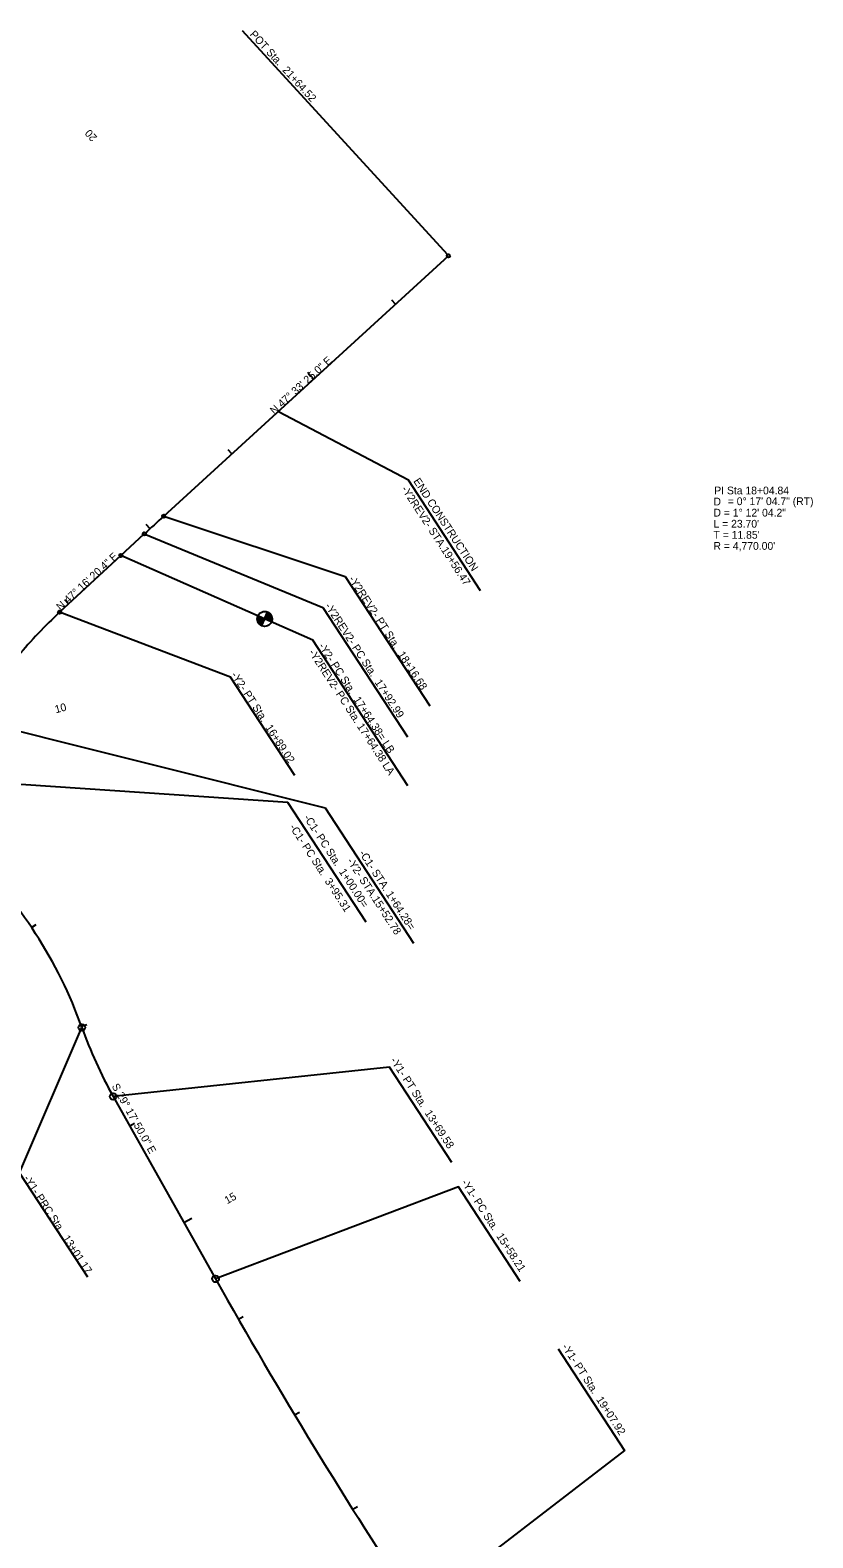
# Model space of a CAD drawing. Extents: x 1636713 to 1642889, y 841520 to 844630.
# Drawn here: x 1640491 to 1641196, y 843029 to 844389 of the extents above; entities that cross this region are included whole.
import ezdxf

# ---------------------------------------------------------------- set-up
doc = ezdxf.new("R2010")
doc.units = 0
for name, color, linetype in [('Exist 4 AWG with gnd feeder circuit in conduit', 7, 'Continuous'), ('Exist 6 AWG with gnd feeder circuit', 7, 'Continuous'), ('Exist 8 AWG with gnd feeder circuit', 7, 'Continuous'), ('Exist 8 AWG with gnd feeder circuit in conduit', 7, 'Continuous'), ('Prop 2 AWG with gnd feeder circuit', 7, 'Continuous'), ('Prop 2 AWG with gnd feeder circuit in conduit', 7, 'Continuous'), ('Prop 4 AWG with gnd feeder circuit', 7, 'Continuous'), ('Prop Clearing and Grubbing', 7, 'Continuous')]:
    doc.layers.add(name, color=color, linetype=linetype)

msp = doc.modelspace()

# ---------------------------------------------------------------- linework, layer by layer
at = {"layer": 'Exist 6 AWG with gnd feeder circuit'}
for p, q in [((1640866.6, 844186.6), (1640682, 844388.4)), ((1640896.6, 843883.4), (1640831.5, 843983.1)), ((1640610.9, 843950.7), (1640774.6, 843896.3)), ((1640593.4, 843934.7), (1640754.5, 843868.4)), ((1640774.6, 843896.3), (1640850.7, 843779.7)), ((1640671.2, 843805.7), (1640517.1, 843864.1)), ((1640701.9, 843858.1), (1640704.6, 843864.3)), ((1640754.5, 843868.4), (1640830.6, 843751.8)), ((1640695.8, 843860.8), (1640701.9, 843858.1)), ((1640699.2, 843852), (1640701.9, 843858.1)), ((1640701.9, 843858.1), (1640699.2, 843852)), ((1640708.1, 843855.4), (1640701.9, 843858.1)), ((1640722.9, 843692.6), (1640411, 843713.6)), ((1640793.3, 843584.7), (1640722.9, 843692.6)), ((1640836.4, 843565.5), (1640756.9, 843687.4))]:
    msp.add_line(p, q, dxfattribs=at)
for points in [[(1640831.5, 843983.1), (1640714.4, 844044.7)], [(1640830.9, 843707.6), (1640745.2, 843838.9), (1640572.4, 843915.3)], [(1640704.7, 843864.2), (1640704.7, 843864.2), (1640702, 843858.1)], [(1640704.8, 843864.2), (1640702.1, 843858)], [(1640704.9, 843864.1), (1640702.2, 843858)], [(1640705, 843864.1), (1640702.3, 843857.9)], [(1640705.2, 843864), (1640702.5, 843857.9)], [(1640705.3, 843863.9), (1640702.6, 843857.8)], [(1640705.4, 843863.9), (1640702.7, 843857.8)], [(1640705.5, 843863.8), (1640702.8, 843857.7)], [(1640705.6, 843863.7), (1640703, 843857.7)], [(1640705.7, 843863.6), (1640703.1, 843857.6)], [(1640705.8, 843863.6), (1640703.2, 843857.6)], [(1640706, 843863.5), (1640703.3, 843857.5)], [(1640706.1, 843863.4), (1640703.4, 843857.4)], [(1640706.2, 843863.3), (1640703.6, 843857.4)], [(1640706.3, 843863.2), (1640703.7, 843857.3)], [(1640706.4, 843863.1), (1640703.8, 843857.3)], [(1640706.5, 843863), (1640703.9, 843857.2)], [(1640706.6, 843862.9), (1640704.1, 843857.2)], [(1640706.7, 843862.8), (1640704.2, 843857.1)], [(1640706.8, 843862.7), (1640704.3, 843857.1)], [(1640706.9, 843862.6), (1640704.4, 843857)], [(1640707, 843862.5), (1640704.5, 843857)], [(1640707.1, 843862.4), (1640704.7, 843856.9)], [(1640707.2, 843862.3), (1640704.8, 843856.8)], [(1640707.3, 843862.1), (1640704.9, 843856.8)], [(1640707.4, 843862), (1640705, 843856.7)], [(1640707.5, 843861.9), (1640705.2, 843856.7)], [(1640707.6, 843861.8), (1640705.3, 843856.6)], [(1640707.6, 843861.6), (1640705.4, 843856.6)], [(1640707.7, 843861.5), (1640705.5, 843856.5)], [(1640707.8, 843861.3), (1640705.7, 843856.5)], [(1640696, 843860.7), (1640695.2, 843858.9)], [(1640696.2, 843860.7), (1640695.2, 843858.5)], [(1640696.3, 843860.6), (1640695.2, 843858.1)], [(1640696.4, 843860.5), (1640695.2, 843857.8)], [(1640696.5, 843860.5), (1640695.2, 843857.5)], [(1640695.9, 843860.8), (1640695.3, 843859.4)], [(1640696.7, 843860.4), (1640695.3, 843857.2)], [(1640696.8, 843860.4), (1640695.3, 843857)], [(1640696.9, 843860.3), (1640695.3, 843856.8)], [(1640697, 843860.3), (1640695.4, 843856.5)], [(1640697.2, 843860.2), (1640695.4, 843856.3)], [(1640695.8, 843860.8), (1640695.5, 843860.1)], [(1640697.3, 843860.2), (1640695.5, 843856.1)], [(1640697.4, 843860.1), (1640695.6, 843856)], [(1640697.5, 843860.1), (1640695.6, 843855.8)], [(1640697.6, 843860), (1640695.7, 843855.6)], [(1640697.8, 843859.9), (1640695.8, 843855.4)], [(1640697.9, 843859.9), (1640695.8, 843855.3)], [(1640698, 843859.8), (1640695.9, 843855.1)], [(1640698.1, 843859.8), (1640696, 843854.9)], [(1640698.3, 843859.7), (1640696.1, 843854.8)], [(1640698.4, 843859.7), (1640696.2, 843854.7)], [(1640698.5, 843859.6), (1640696.2, 843854.5)], [(1640698.6, 843859.6), (1640696.3, 843854.4)], [(1640698.7, 843859.5), (1640696.4, 843854.2)], [(1640698.9, 843859.5), (1640696.5, 843854.1)], [(1640699, 843859.4), (1640696.6, 843854)], [(1640699.1, 843859.4), (1640696.7, 843853.9)], [(1640699.2, 843859.3), (1640696.8, 843853.8)], [(1640699.4, 843859.2), (1640696.9, 843853.7)], [(1640699.5, 843859.2), (1640697, 843853.6)], [(1640699.6, 843859.1), (1640697.1, 843853.4)], [(1640699.7, 843859.1), (1640697.2, 843853.3)], [(1640699.9, 843859), (1640697.3, 843853.2)], [(1640700, 843859), (1640697.4, 843853.1)], [(1640700.1, 843858.9), (1640697.5, 843853.1)], [(1640700.2, 843858.9), (1640697.6, 843853)], [(1640700.3, 843858.8), (1640697.7, 843852.9)], [(1640700.5, 843858.8), (1640697.8, 843852.8)], [(1640700.6, 843858.7), (1640697.9, 843852.7)], [(1640700.7, 843858.6), (1640698.1, 843852.6)], [(1640700.8, 843858.6), (1640698.2, 843852.5)], [(1640701, 843858.5), (1640698.3, 843852.5)], [(1640701.1, 843858.5), (1640698.4, 843852.4)], [(1640701.2, 843858.4), (1640698.5, 843852.3)], [(1640701.3, 843858.4), (1640698.6, 843852.3)], [(1640701.5, 843858.3), (1640698.7, 843852.2)], [(1640701.6, 843858.3), (1640698.9, 843852.1)], [(1640701.7, 843858.2), (1640699, 843852.1)], [(1640701.8, 843858.2), (1640699.1, 843852), (1640699.1, 843852)], [(1640707.9, 843861.2), (1640705.8, 843856.4)], [(1640708, 843861), (1640705.9, 843856.4)], [(1640708, 843860.9), (1640706, 843856.3)], [(1640708.1, 843860.7), (1640706.1, 843856.3)], [(1640708.2, 843860.5), (1640706.3, 843856.2)], [(1640708.2, 843860.3), (1640706.4, 843856.1)], [(1640708.3, 843860.2), (1640706.5, 843856.1)], [(1640708.4, 843859.9), (1640706.6, 843856)], [(1640708.4, 843859.7), (1640706.8, 843856)], [(1640708.5, 843859.5), (1640706.9, 843855.9)], [(1640708.5, 843859.3), (1640707, 843855.9)], [(1640708.6, 843859.1), (1640707.1, 843855.8)], [(1640708.6, 843858.8), (1640707.3, 843855.8)], [(1640708.6, 843858.5), (1640707.4, 843855.7)], [(1640708.6, 843858.2), (1640707.5, 843855.7)], [(1640708.6, 843857.9), (1640707.6, 843855.6)], [(1640708.6, 843857.5), (1640707.7, 843855.5)], [(1640708.5, 843857), (1640707.9, 843855.5)], [(1640708.4, 843856.3), (1640708, 843855.4)], [(1640729.2, 843716.8), (1640671.2, 843805.7)], [(1640756.9, 843687.4), (1640417, 843772.6)], [(1640542.5, 843264.4), (1640480.9, 843358.7), (1640537.2, 843489.7)], [(1640870.7, 843368), (1640814.6, 843454), (1640565.4, 843427.4)], [(1640932.3, 843260.7), (1640876.6, 843346.1), (1640657.7, 843262.9)], [(1640966.6, 843199.8), (1641026.4, 843108.2), (1640839.8, 842964.5)]]:
    msp.add_lwpolyline(points, dxfattribs=at)
for centre, radius in [((1640867.6, 844185.4), 1.5), ((1640610.9, 843950.7), 1.5), ((1640593.4, 843934.7), 1.5), ((1640572.4, 843915.3), 1.5), ((1640572.4, 843915.3), 1.5), ((1640517.1, 843864.1), 1.5), ((1640701.9, 843858.1), 6.71), ((1640537.2, 843489.7), 3), ((1640565.4, 843427.4), 3), ((1640657.7, 843262.9), 3)]:
    msp.add_circle(centre, radius, dxfattribs=at)
for start, end in [(336.1709, 66.1709), (156.1709, 246.1709)]:
    msp.add_arc((1640701.9, 843858.1), 6.71, start, end, dxfattribs=at)
at = {"layer": 'Exist 8 AWG with gnd feeder circuit'}
for p, q in [((1640610.9, 843950.7), (1640867.6, 844185.4)), ((1640572.4, 843915.3), (1640593.4, 843934.7)), ((1640517.1, 843864.1), (1640572.4, 843915.3)), ((1640565.4, 843427.4), (1640657.7, 843262.9))]:
    msp.add_line(p, q, dxfattribs=at)
for centre, radius, start, end in [((1643830, 840430.7), 4770, 132.443, 132.7277), ((1640788.5, 843570.3), 400, 132.7277, 140.5319), ((1640160.1, 843356.2), 400, 19.498, 46.5509), ((1640914.2, 843623.2), 400, 199.498, 209.2972), ((1644817.6, 845597.1), 4770, 209.2972, 213.4979)]:
    msp.add_arc(centre, radius, start, end, dxfattribs=at)
at = {"layer": 'Prop 2 AWG with gnd feeder circuit in conduit'}
for p, q in [((1640746.2, 844074.4), (1640740.8, 844080.3)), ((1640629.2, 843313.7), (1640636.2, 843317.6))]:
    msp.add_line(p, q, dxfattribs=at)
at = {"layer": 'Prop 4 AWG with gnd feeder circuit'}
for p, q in [((1640820, 844141.9), (1640816.6, 844145.6)), ((1640672.4, 844006.9), (1640669, 844010.6)), ((1640598.6, 843939.4), (1640595.2, 843943.1)), ((1640525.1, 843871.6), (1640521.7, 843875.2)), ((1640491.8, 843579.8), (1640495.9, 843582.6)), ((1640536.8, 843490.8), (1640541.5, 843492.4)), ((1640580.3, 843400.9), (1640584.6, 843403.4)), ((1640678.3, 843226.6), (1640682.6, 843229.1)), ((1640728.9, 843140.3), (1640733.2, 843142.9)), ((1640781.3, 843055.2), (1640785.5, 843057.8))]:
    msp.add_line(p, q, dxfattribs=at)
at = {"layer": 'Prop Clearing and Grubbing'}
msp.add_line((1640714.4, 844044.7), (1640714, 844045), dxfattribs=at)

# ---------------------------------------------------------------- texts
at = {"layer": 'Exist 4 AWG with gnd feeder circuit in conduit'}
for s, rotation, p in [('20', 132.443, (1640551.4, 844292.5)), ('10', 14.3786, (1640513.7, 843773)), ('15', 29.2972, (1640668.1, 843330.2))]:
    msp.add_text(s, height=7, rotation=rotation, dxfattribs=at).set_placement(p)
at = {"layer": 'Exist 6 AWG with gnd feeder circuit'}
for s, rotation, p in [('POT Sta.  21+64.52', 312.443, (1640688, 844384.8)), ('END CONSTRUCTION', 303.1259, (1640835.7, 843982.3)), ('-Y2REV2- STA.19+56.47', 303.1259, (1640824.8, 843975.2)), ('-Y2REV2- PT Sta.  18+16.68', 303.1259, (1640777.3, 843894.1)), ('-Y2REV2- PC Sta.  17+92.99', 303.1259, (1640755.9, 843869.7)), ('-Y2- PC Sta.  17+64.38= LB', 303.1259, (1640750.1, 843833.7)), ('-Y2REV2- PC Sta. 17+64.38 LA', 303.1259, (1640741.3, 843827.9)), ('-Y2- PT Sta.  16+89.02', 303.1259, (1640671.3, 843807.6)), ('-C1- PC Sta.  3+95.31', 303.1259, (1640723.9, 843670.4)), ('-C1- PC Sta.  1+00.00=', 303.1259, (1640736.8, 843678.9)), ('-C1- STA. 1+64.28=', 303.1259, (1640786.7, 843646.9)), ('-Y2- STA.15+52.78', 303.1259, (1640775.8, 843639.8)), ('-Y1- PT Sta.  13+69.58', 303.1259, (1640814.9, 843460)), ('-Y1- PRC Sta.  13+01.17', 303.1259, (1640484.2, 843353.7)), ('-Y1- PC Sta.  15+58.21', 303.1259, (1640878.9, 843349.9)), ('-Y1- PT Sta.  19+07.92', 303.1259, (1640969.5, 843201.7))]:
    msp.add_text(s, height=7, rotation=rotation, dxfattribs=at).set_placement(p)
at = {"layer": 'Exist 8 AWG with gnd feeder circuit in conduit'}
for s, rotation, p in [('N 47%%d 33\' 25.0" E', 42.443, (1640710.6, 844042.1)), ('N 47%%d 16\' 20.4" E', 42.7277, (1640518, 843865.2)), ('S 29%%d 17\' 50.0" E', 299.2972, (1640563.8, 843436.8))]:
    msp.add_text(s, height=7, rotation=rotation, dxfattribs=at).set_placement(p)
at = {"layer": 'Prop 2 AWG with gnd feeder circuit'}
for s, p in [('PI Sta 18+04.84', (1641107.2, 843970.4)), ('D', (1641106.5, 843960.4)), ('D = 1%%d 12\' 04.2"', (1641106.5, 843950.4)), ('= 0%%d 17\' 04.7" (RT)', (1641119.4, 843960.7)), ("L = 23.70'", (1641106.5, 843940.4)), ("T = 11.85'", (1641106.5, 843930.4)), ("R = 4,770.00'", (1641106.5, 843920.4))]:
    msp.add_text(s, height=7, dxfattribs=at).set_placement(p)

doc.saveas('drawing.dxf')
